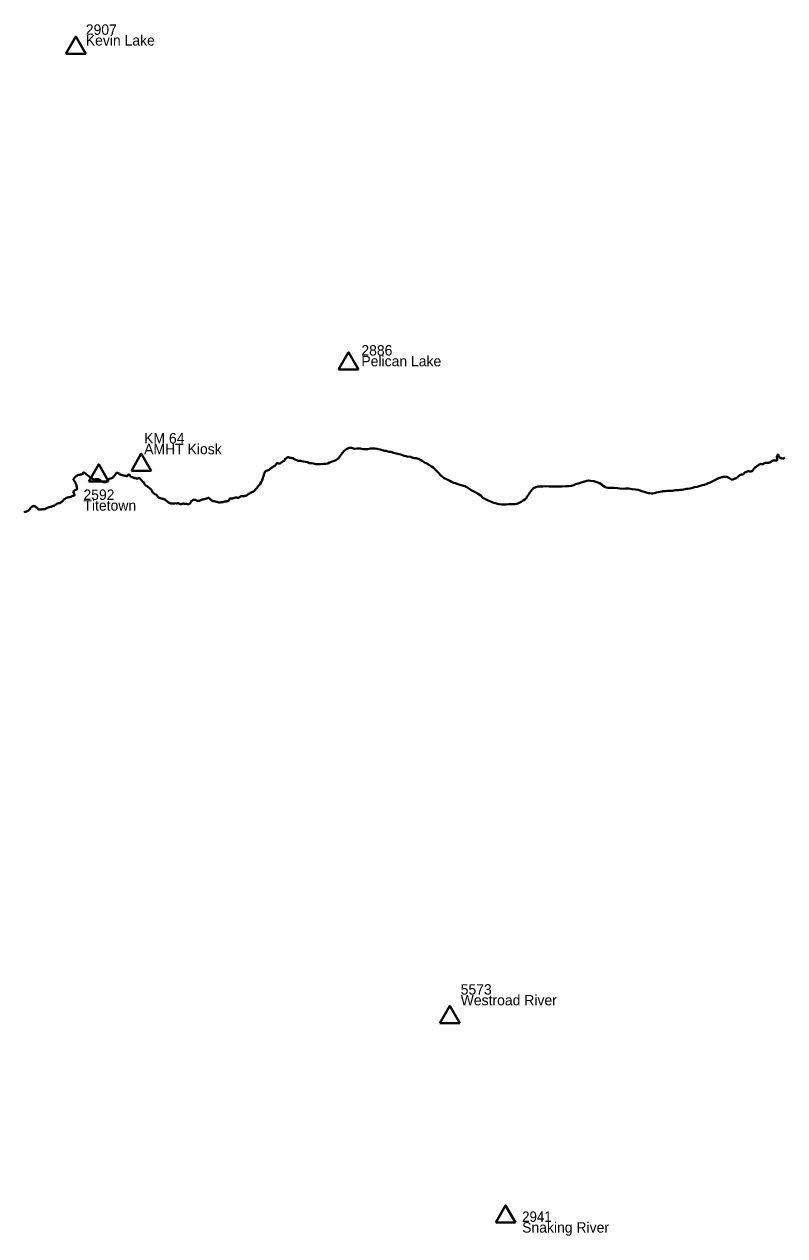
# Model space of a CAD drawing. Extents: x 322505 to 642419, y 5806860 to 5919753.
# Drawn here: x 446724 to 472235, y 5879111 to 5919753 of the extents above; entities that cross this region are included whole.
import ezdxf

# ---------------------------------------------------------------- set-up
doc = ezdxf.new("R2010")
doc.units = 0
doc.header["$LTSCALE"] = 140
for name, color, linetype, lineweight in [('1', 7, 'Continuous', 40), ('3', 7, 'Continuous', 40), ('6', 7, 'Continuous', 40)]:
    doc.layers.add(name, color=color, linetype=linetype, lineweight=lineweight)

msp = doc.modelspace()

# ---------------------------------------------------------------- linework, layer by layer
at = {"layer": '1'}
for p, q in [((448120.9, 5918759.9), (448786.2, 5918759.9)), ((457270.7, 5908171.9), (457936.1, 5908171.9)), ((448889.7, 5904414.4), (449555.1, 5904414.4)), ((460664.6, 5886247.9), (461330, 5886247.9)), ((462539.9, 5879552.4), (463205.3, 5879552.4))]:
    msp.add_line(p, q, dxfattribs=at)
for points in [[(448786.2, 5918759.9), (448453.5, 5919336.1), (448120.9, 5918759.9)], [(457936.1, 5908171.9), (457603.4, 5908748.1), (457270.7, 5908171.9)], [(449555.1, 5904414.4), (449222.4, 5904990.6), (448889.7, 5904414.4)], [(461330, 5886247.9), (460997.3, 5886824.1), (460664.6, 5886247.9)], [(463205.3, 5879552.4), (462872.6, 5880128.6), (462539.9, 5879552.4)]]:
    msp.add_lwpolyline(points, dxfattribs=at)
at = {"layer": '3'}
msp.add_line((450317, 5904771.4), (450982.4, 5904771.4), dxfattribs=at)
msp.add_lwpolyline([(450982.4, 5904771.4), (450649.7, 5905347.6), (450317, 5904771.4)], dxfattribs=at)
at = {"layer": '6'}
for points in [[(455756, 5905178), (455809.3, 5905147.4), (455908.2, 5905112.1), (455986.3, 5905101.7), (456082.9, 5905087.7), (456151, 5905077.7), (456222.5, 5905061.3), (456292.1, 5905032.3), (456360.4, 5905026.1), (456424.6, 5905012.6), (456508.4, 5904994.2), (456592, 5904992.3), (456667.1, 5904997.1), (456758.7, 5905006.1), (456829.8, 5905004.8), (456905.6, 5905020.9), (456959.3, 5905045.8), (457053.6, 5905079.9), (457126.1, 5905105), (457174.6, 5905125.2), (457250.3, 5905186.7), (457284.7, 5905221.5), (457314.2, 5905260.3), (457357.3, 5905317.3), (457398.9, 5905371.8), (457450.5, 5905447.3), (457497.2, 5905480.1), (457550.1, 5905512.6), (457630.2, 5905538.6), (457701.8, 5905547.4), (457770.3, 5905521), (457809.9, 5905513), (457875.5, 5905515.3), (457933.9, 5905520.3), (457997.8, 5905520.9), (458092.6, 5905496.8), (458138.5, 5905497.9), (458234.6, 5905498.7), (458334.6, 5905523.7), (458424.4, 5905522.7), (458492.9, 5905519), (458559.5, 5905505.3), (458596.3, 5905493.3), (458664.4, 5905482.1), (458803.5, 5905446.9), (458864.4, 5905441.1), (458925.5, 5905417.6), (458966.2, 5905409.1), (459018.5, 5905406.3), (459111.6, 5905373.6), (459200.4, 5905355), (459356.7, 5905313.8), (459467.2, 5905280.1), (459530.3, 5905263.5)], [(459530.3, 5905263.5), (459557.1, 5905256.4), (459679.7, 5905239.7), (459760.4, 5905208.9), (459769.5, 5905206.7)], [(472239, 5905209), (472217, 5905195), (472196, 5905184), (472189, 5905184), (472167, 5905187), (472161, 5905187), (472140, 5905190), (472118, 5905193), (472099, 5905200), (472078, 5905212), (472074, 5905214), (472050, 5905225), (472036, 5905243), (472029, 5905267), (472025, 5905287), (472021, 5905302), (472009, 5905319), (471999, 5905315), (471993, 5905304), (471990, 5905290), (471981, 5905272), (471977, 5905260), (471970, 5905238), (471972, 5905213), (471974, 5905208), (471976, 5905187), (471979, 5905165), (471981, 5905143)], [(455473, 5905161), (455468, 5905143), (455451, 5905120), (455439, 5905111), (455413, 5905095), (455400, 5905085), (455385, 5905075), (455361, 5905061), (455343, 5905046), (455320, 5905026), (455299, 5905017), (455293, 5905016), (455268, 5905022), (455249, 5905022), (455232, 5905034), (455226, 5905034), (455203, 5905025), (455190, 5905016), (455186, 5905009), (455180, 5904991), (455163, 5904968), (455153, 5904958), (455128, 5904941), (455117, 5904933), (455103, 5904926), (455090, 5904920), (455068, 5904908), (455049, 5904892), (455036, 5904882), (455023, 5904873), (455008, 5904862), (454988, 5904845), (454964, 5904832), (454959, 5904829), (454938, 5904807), (454918, 5904798), (454903, 5904793), (454884, 5904788), (454866, 5904779), (454847, 5904771), (454825, 5904773), (454823, 5904774.4)], [(455756, 5905178), (455753, 5905191), (455743, 5905195), (455719, 5905198), (455706, 5905199), (455682, 5905203), (455668, 5905203), (455653, 5905202), (455640, 5905203), (455628, 5905207), (455613, 5905214), (455590, 5905226), (455575, 5905231), (455554, 5905226), (455532, 5905206), (455518, 5905195), (455506, 5905183), (455486, 5905179), (455475, 5905174), (455473, 5905161)], [(459769.5, 5905206.7), (459812.2, 5905196.1), (459871.8, 5905191.6), (459974, 5905166), (460008, 5905136.4)], [(460008, 5905136.4), (460073.3, 5905102.8), (460146.9, 5905055), (460203.3, 5905024.5), (460285.3, 5904984.8), (460350.1, 5904943.2), (460388.8, 5904921.1), (460446.4, 5904879), (460480.7, 5904840.9), (460536.9, 5904786.3), (460590.1, 5904738.4), (460628, 5904688.3), (460685.1, 5904631.1), (460757, 5904572.2), (460810.7, 5904528), (460883.4, 5904486.8), (460951, 5904456.4), (460994.5, 5904432.4), (461055.7, 5904400.2), (461118.5, 5904370.2), (461190.2, 5904353.3), (461246.3, 5904330.5), (461302.5, 5904309), (461454.2, 5904270.4), (461502, 5904251.8), (461570.7, 5904219.2), (461636.9, 5904176.2), (461717.2, 5904118), (461785.1, 5904085.8), (461853.1, 5904057.9), (461953.8, 5903999.6), (462037.1, 5903940.9), (462102.4, 5903868.5), (462153.2, 5903843.7), (462223.9, 5903806.6), (462290.2, 5903775), (462339.9, 5903751.6), (462422.1, 5903717), (462479.1, 5903700.4), (462523, 5903682.3), (462640.8, 5903653.1), (462745.5, 5903640.1), (462816.8, 5903641), (462885.3, 5903639.7), (462984.6, 5903656.6), (463089.2, 5903653.8), (463180.8, 5903657.5), (463240.5, 5903666.1), (463275.5, 5903677.4), (463350.3, 5903708.5), (463389.6, 5903735.9), (463458.3, 5903779), (463516.7, 5903809.4), (463569.2, 5903853.1), (463587.3, 5903901.9), (463626.1, 5903957.3), (463660.1, 5904003.1), (463685, 5904046.1), (463733.6, 5904099.2), (463762, 5904150.7), (463804.6, 5904195.5), (463879.5, 5904227.8), (463947.9, 5904246.8), (464004.2, 5904248.2), (464045.2, 5904246.1), (464117.8, 5904248.6), (464223.7, 5904253.7), (464327.1, 5904251.2), (464377.2, 5904244.6), (464488.4, 5904244.8), (464582.6, 5904249.5), (464668.8, 5904250.1), (464763.8, 5904250.9), (464886.5, 5904253.7), (464994.7, 5904260.6), (465077.5, 5904264.1), (465157.3, 5904295.8), (465177.9, 5904301.2), (465209.8, 5904321.1)], [(471981, 5905143), (471980, 5905123), (471973, 5905118), (471950, 5905117), (471927, 5905117), (471916, 5905118), (471896, 5905123), (471880, 5905125), (471856, 5905121), (471846, 5905118), (471825, 5905107), (471803, 5905094), (471784, 5905082), (471774, 5905075), (471755, 5905067), (471733, 5905056), (471710, 5905046), (471690, 5905040), (471667, 5905039), (471664, 5905038), (471592, 5905038), (471581, 5905036), (471557, 5905024), (471538, 5905016), (471518, 5905007), (471496, 5905000), (471478, 5904995), (471458, 5904995), (471436, 5904997), (471417, 5905001), (471394, 5904998), (471386, 5904995), (471369, 5904975), (471352, 5904959), (471331, 5904946), (471319, 5904937), (471301, 5904924), (471279, 5904908), (471275, 5904902), (471254, 5904889), (471234, 5904876), (471213, 5904863), (471194, 5904839), (471182, 5904820), (471173, 5904802), (471161, 5904782), (471151, 5904774), (471128, 5904764), (471115, 5904757), (471092, 5904750), (471070, 5904751), (471064, 5904751), (471043, 5904758), (471033, 5904761), (471009, 5904762), (470988, 5904755), (470970, 5904746), (470948, 5904732), (470937, 5904728), (470916, 5904726), (470896, 5904718), (470880, 5904705), (470867, 5904683), (470854, 5904663), (470834, 5904653), (470813, 5904649), (470804, 5904647), (470784, 5904646), (470766, 5904644), (470747, 5904636), (470729, 5904625), (470713, 5904611), (470697, 5904602), (470676, 5904584), (470663, 5904566), (470650, 5904555), (470634, 5904540), (470622, 5904532), (470603, 5904522), (470577, 5904517), (470556, 5904516), (470533, 5904508)], [(448036, 5903782), (448052, 5903805), (448066, 5903819), (448094, 5903837), (448119, 5903853), (448132, 5903861), (448147, 5903868), (448170, 5903876), (448193, 5903881), (448205, 5903885), (448219, 5903889), (448234, 5903890), (448247, 5903890), (448260, 5903892), (448282, 5903901), (448304, 5903912), (448315, 5903915), (448336, 5903927), (448353, 5903934), (448372, 5903928), (448394, 5903937), (448405, 5903956), (448405, 5903972), (448402, 5903985), (448396, 5903997), (448388, 5904017), (448385, 5904037), (448378, 5904050), (448369, 5904073), (448369, 5904083), (448384, 5904106), (448406, 5904113), (448423, 5904126), (448436, 5904130), (448451, 5904136), (448475, 5904147), (448497, 5904160), (448505, 5904167), (448507, 5904174), (448503, 5904189), (448490, 5904207), (448483, 5904230), (448477, 5904252), (448477, 5904272), (448474, 5904296), (448470, 5904308), (448464, 5904323), (448459, 5904335), (448446, 5904357), (448439, 5904370), (448430, 5904392), (448418, 5904415), (448404, 5904435), (448397, 5904444), (448382, 5904454), (448375, 5904473), (448378, 5904492), (448383, 5904505), (448388, 5904517), (448405, 5904540), (448419, 5904548), (448433, 5904555), (448449, 5904578), (448460, 5904589), (448475, 5904598), (448496, 5904612), (448518, 5904632), (448529, 5904637), (448542, 5904638), (448557, 5904638), (448580, 5904641), (448601, 5904647), (448621, 5904646), (448634, 5904648), (448647, 5904651), (448672, 5904657), (448691, 5904666), (448698, 5904679), (448699, 5904694)], [(448699, 5904694), (448700.1, 5904706.8), (448710.8, 5904711.4), (448730.7, 5904711.4), (448947.1, 5904548.7), (448970.1, 5904530.3), (448983.9, 5904521.1), (449003.9, 5904508.8), (449016.2, 5904502.7), (449033, 5904493.5), (449038.9, 5904492.2)], [(449039.5, 5904492.1), (449062.2, 5904487.3), (449068.3, 5904485.8), (449089.8, 5904485.8), (449112.8, 5904487.3), (449126.6, 5904488.9), (449143.5, 5904491.9), (449160.4, 5904493.5), (449187, 5904493), (449219.3, 5904486.9), (449235.2, 5904482.5)], [(449235.2, 5904482.5), (449248, 5904479), (449266.3, 5904460.8), (449292.4, 5904441.2), (449309.4, 5904429.4), (449334.2, 5904413.7), (449353.8, 5904407.2), (449369.5, 5904402), (449383.8, 5904395.4), (449413.9, 5904387.6), (449445.2, 5904394.1), (449473.9, 5904405.9), (449475.7, 5904407.6)], [(449475.7, 5904407.6), (449488.3, 5904420.3), (449501.4, 5904443.8), (449519.6, 5904463.4), (449539.2, 5904476.4), (449551, 5904486.9), (449570.6, 5904497.3), (449584.9, 5904505.2), (449600, 5904511)], [(449651.4, 5904523), (449646, 5904521), (449628, 5904510), (449615, 5904509), (449600, 5904511)], [(450380, 5904543), (450360, 5904557), (450336, 5904559), (450322, 5904566), (450303, 5904574), (450280, 5904590), (450266, 5904614), (450261, 5904629), (450251, 5904647), (450243, 5904652), (450228, 5904648), (450214, 5904637), (450194, 5904626), (450187, 5904614), (450180, 5904592), (450168, 5904590), (450145, 5904605), (450123, 5904602), (450104, 5904603), (450092, 5904606), (450074, 5904611), (450050, 5904616), (450028, 5904624), (450017, 5904626), (450002, 5904630), (449983, 5904634), (449970, 5904638), (449956, 5904643), (449936, 5904649), (449923, 5904665), (449906, 5904678), (449882, 5904697), (449855, 5904706), (449839, 5904708), (449824, 5904699), (449810, 5904680), (449791, 5904667), (449784, 5904659), (449777, 5904641), (449770, 5904629), (449745, 5904604), (449733, 5904590), (449717, 5904570), (449702, 5904550), (449684, 5904536), (449670, 5904530), (449651.4, 5904523)], [(451192, 5903924), (451191, 5903931), (451183, 5903943), (451171, 5903951), (451157, 5903961), (451139, 5903976), (451107, 5903992), (451083, 5904007), (451070, 5904014), (451048, 5904028), (451037, 5904037), (451024, 5904056), (451017, 5904070), (451009, 5904096), (451004, 5904115), (450997, 5904128), (450982, 5904147), (450968, 5904156), (450952, 5904166), (450939, 5904181), (450930, 5904192), (450914, 5904207), (450894, 5904216), (450872, 5904230), (450855, 5904245), (450839, 5904256), (450824, 5904262), (450811, 5904270), (450799, 5904281), (450786, 5904295), (450772, 5904313), (450767, 5904327), (450763, 5904339), (450752, 5904363), (450743, 5904376), (450727, 5904389), (450701, 5904402), (450691, 5904410), (450682, 5904423), (450676, 5904438), (450662, 5904460), (450638, 5904480), (450626, 5904491), (450604, 5904510), (450582, 5904524), (450564, 5904528), (450550, 5904529), (450531, 5904525), (450519, 5904507), (450511, 5904504), (450488, 5904510), (450466, 5904518), (450443, 5904533), (450433, 5904532), (450411, 5904524), (450395, 5904529), (450380, 5904543)], [(454825, 5904773), (454821.3, 5904757.8), (454797.6, 5904734.1), (454797.6, 5904721.3), (454783, 5904697.7), (454772.1, 5904675.8), (454761.2, 5904648.5), (454761.2, 5904632.1), (454755.7, 5904610.2), (454746.6, 5904584.7), (454732, 5904550.1), (454730.2, 5904533.7), (454717.5, 5904493.6), (454706.5, 5904462.6), (454690.1, 5904428), (454675.6, 5904387.9), (454639.1, 5904333.2), (454624.6, 5904315), (454580.9, 5904271.3), (454539, 5904213), (454520.8, 5904191.1), (454497.1, 5904167.4), (454480.7, 5904143.8), (454473.4, 5904132.8), (454460.6, 5904111), (454440.6, 5904092.7), (454438, 5904085)], [(465209.8, 5904321.1), (465261.3, 5904330.9), (465350.6, 5904357.8), (465409.7, 5904380.4), (465478.6, 5904401), (465533.4, 5904417.6), (465591, 5904439.3), (465648, 5904447.7), (465717.2, 5904435.2), (465827.8, 5904424.9), (465896.6, 5904406.1), (465961.4, 5904383.7), (466025.6, 5904352.4), (466107.2, 5904299.6), (466148.6, 5904264.8), (466193.9, 5904231.1), (466247.8, 5904213.3), (466309.4, 5904200), (466388.5, 5904204.7), (466458.1, 5904197.3), (466517.3, 5904196.3), (466623.8, 5904188.2), (466701.1, 5904184), (466824, 5904171.6), (466889.5, 5904178.5), (466994.4, 5904176.2), (467113, 5904153.9), (467225, 5904144.7), (467311.8, 5904134.5), (467352.7, 5904128.1), (467444.2, 5904093.7), (467552.9, 5904054.2), (467583.4, 5904043.1), (467663.8, 5904023.3), (467699.4, 5904019.7), (467760.4, 5904015.4), (467793.9, 5904010.5), (467853.2, 5904019.1), (467900.4, 5904032.4), (467937.1, 5904040), (467993.1, 5904055.3), (468118.5, 5904078.2), (468159.1, 5904086.8), (468238.1, 5904092.3), (468291.3, 5904100.5), (468378.1, 5904104.7), (468460.5, 5904105.2), (468512.4, 5904115.5), (468575.5, 5904123.8), (468671.8, 5904123.4), (468721, 5904130.2), (468777.8, 5904137.7), (468836, 5904148.9), (468895.3, 5904156.2), (468942.1, 5904163.4), (468987.6, 5904171.3), (469047.1, 5904177.8), (469103.9, 5904189.9), (469204.6, 5904218.5), (469299.7, 5904238.6), (469392.9, 5904265.3), (469470.4, 5904286.5), (469534.9, 5904304.4), (469602, 5904328.2), (469663.8, 5904355.7), (469732, 5904384.1), (469773.5, 5904406.6), (469798.4, 5904416.9), (469813.3, 5904420.6)], [(469813.3, 5904420.6), (469831, 5904426), (469848, 5904438), (469870, 5904451), (469888, 5904462), (469912, 5904472), (469950, 5904491), (469965, 5904499), (469989, 5904509), (470008, 5904517), (470015, 5904522), (470038, 5904526), (470051, 5904531), (470074, 5904539), (470092, 5904548), (470114, 5904556), (470133, 5904563), (470155, 5904572), (470178, 5904575), (470200, 5904575), (470223, 5904574), (470249, 5904572), (470271, 5904570), (470290, 5904566), (470312, 5904557), (470335, 5904548), (470358, 5904538), (470379, 5904530), (470397, 5904523), (470407, 5904511), (470423, 5904492), (470433, 5904485), (470452, 5904476), (470473, 5904476), (470496, 5904485), (470513, 5904497), (470533, 5904508)], [(453554, 5903756), (453576, 5903761), (453589, 5903775), (453598, 5903799), (453602, 5903813), (453610, 5903833), (453619, 5903841), (453638, 5903845), (453659, 5903847), (453673, 5903846), (453696, 5903846), (453708, 5903847), (453727, 5903851), (453734, 5903853), (453754, 5903855), (453771, 5903860), (453791, 5903872), (453808, 5903876), (453831, 5903877), (453854, 5903873), (453868, 5903870), (453881, 5903867), (453896, 5903868), (453920, 5903874), (453939, 5903884), (453952, 5903892), (453965, 5903898), (453983, 5903910), (454000, 5903917), (454014, 5903919), (454038, 5903925), (454046, 5903926), (454092, 5903926), (454098, 5903927), (454120, 5903931), (454132, 5903933), (454153, 5903938), (454170, 5903942), (454183, 5903948), (454197, 5903954), (454219, 5903979), (454240, 5903991), (454262, 5904004), (454276, 5904011), (454299, 5904025), (454304, 5904028), (454332, 5904048), (454352, 5904060), (454359, 5904063), (454380, 5904065), (454391, 5904067), (454405, 5904071), (454420, 5904077), (454438, 5904085)], [(446920.5, 5903505), (446923, 5903514), (446939, 5903535), (446964, 5903554), (446985, 5903570), (447000, 5903578), (447015, 5903591), (447024, 5903592), (447043, 5903588), (447057, 5903588), (447076, 5903587), (447093, 5903584), (447101, 5903578), (447117, 5903554), (447136, 5903543), (447159, 5903525), (447173, 5903516), (447196, 5903491), (447218, 5903476), (447240, 5903471), (447263, 5903471), (447286, 5903475), (447305, 5903478), (447329, 5903483), (447340, 5903485), (447361, 5903487), (447383, 5903487), (447388, 5903488), (447412, 5903491), (447433, 5903499), (447453, 5903511), (447476, 5903514), (447495, 5903521), (447515, 5903536), (447539, 5903546), (447551, 5903550), (447575, 5903556), (447597, 5903562), (447613, 5903566), (447635, 5903573), (447655, 5903580), (447665, 5903584), (447689, 5903590), (447699, 5903593), (447718, 5903601), (447735, 5903612), (447750, 5903626), (447768, 5903636), (447781, 5903642), (447794, 5903647), (447806, 5903652), (447823, 5903659), (447838, 5903673), (447852, 5903680), (447864, 5903687), (447877, 5903690), (447892, 5903691), (447906, 5903691), (447919, 5903692), (447940, 5903697), (447954, 5903708), (447967, 5903718), (447979, 5903731), (447993, 5903742), (448008, 5903755), (448032, 5903778), (448036, 5903782)], [(451630, 5903670), (451617, 5903685), (451605, 5903692), (451581, 5903698), (451568, 5903705), (451556, 5903717), (451534, 5903738), (451511, 5903752), (451496, 5903767), (451472, 5903778), (451459, 5903796), (451438, 5903813), (451426, 5903820), (451410, 5903825), (451389, 5903827), (451374, 5903830), (451358, 5903835), (451345, 5903840), (451331, 5903843), (451318, 5903847), (451304, 5903851), (451283, 5903858), (451261, 5903861), (451245, 5903867), (451231, 5903874), (451207, 5903889), (451197, 5903903), (451192, 5903924)], [(452236.4, 5903655.3), (452234, 5903654), (452213, 5903647), (452202, 5903649), (452184, 5903659), (452173, 5903663), (452141, 5903663), (452128, 5903665), (452103, 5903667), (452089, 5903667), (452068, 5903675), (452057, 5903672), (452041, 5903664), (452029, 5903661), (452016, 5903660), (451993, 5903658), (451971, 5903658), (451948, 5903662), (451934, 5903669), (451912, 5903678), (451890, 5903685), (451878, 5903687), (451865, 5903686), (451847, 5903679), (451831, 5903678), (451783, 5903682), (451771, 5903676), (451757, 5903670), (451735, 5903673), (451714, 5903670), (451701, 5903671), (451687, 5903674), (451675, 5903677), (451651, 5903676), (451630, 5903670)], [(452329, 5903753), (452319, 5903739), (452313, 5903726), (452307, 5903712), (452300, 5903699), (452280, 5903675), (452269, 5903667), (452247, 5903661), (452236.4, 5903655.3)], [(452329, 5903753), (452337, 5903761), (452353, 5903764), (452364, 5903773), (452370.5, 5903779.1)], [(452370.5, 5903779.1), (452380, 5903788), (452402, 5903795), (452407, 5903796), (452429, 5903800), (452452, 5903797), (452473, 5903794), (452498, 5903778), (452521, 5903766), (452545, 5903766), (452558, 5903767), (452570, 5903767), (452584, 5903768), (452608, 5903769), (452631, 5903778), (452651, 5903787), (452665, 5903795), (452678, 5903802), (452691, 5903808), (452706, 5903811), (452722, 5903815), (452737, 5903817), (452751, 5903817), (452768, 5903819), (452792, 5903828), (452810, 5903836), (452822, 5903840), (452843, 5903844), (452855, 5903848), (452869, 5903853), (452885, 5903857), (452895, 5903866), (452911, 5903869), (452931, 5903858), (452943, 5903845), (452959, 5903824), (452967, 5903808), (452989, 5903794), (453009, 5903786), (453033, 5903768), (453055, 5903756), (453077, 5903751), (453100, 5903751), (453106, 5903750), (453125, 5903743), (453148, 5903738), (453167, 5903735), (453180, 5903734), (453199, 5903731), (453220, 5903725), (453225, 5903724), (453248, 5903714), (453258, 5903711), (453272, 5903712), (453284, 5903712), (453302, 5903713), (453318, 5903716), (453336, 5903715), (453357, 5903718), (453375, 5903723), (453386, 5903723), (453406, 5903725), (453421, 5903729), (453443, 5903740), (453466, 5903741), (453481, 5903743), (453496, 5903746), (453518, 5903750), (453543, 5903754), (453554, 5903756)], [(446724.1, 5903377.9), (446725, 5903379), (446735, 5903390), (446747, 5903397), (446769, 5903401), (446792, 5903405), (446814, 5903411), (446828, 5903418), (446852, 5903428), (446862, 5903433), (446879, 5903451), (446903, 5903469), (446913, 5903477), (446918, 5903496), (446920.5, 5903505)]]:
    msp.add_lwpolyline(points, dxfattribs=at)

# ---------------------------------------------------------------- texts
at = {"layer": '1'}
for s, p in [('2907', (448789.4, 5919397.7)), ('Kevin Lake', (448789.4, 5919037.7)), ('2886', (458032.9, 5908637.7)), ('Pelican Lake', (458032.9, 5908277.7)), ('2592', (448709.6, 5903794.6)), ('Titetown', (448709.6, 5903434.6)), ('5573', (461364.1, 5887201)), ('Westroad River', (461364.1, 5886841)), ('Snaking River', (463425.3, 5879216.8))]:
    msp.add_text(s, height=350, dxfattribs=at).set_placement(p)
at = {"layer": '1', "width": 0.95}
msp.add_text('2941', height=350, dxfattribs=at).set_placement((463425.3, 5879576.8))
at = {"layer": '3'}
for s, p in [('AMHT Kiosk', (450746.8, 5905328.7)), ('KM 64', (450746.8, 5905688.7))]:
    msp.add_text(s, height=350, dxfattribs=at).set_placement(p)

doc.saveas('drawing.dxf')
